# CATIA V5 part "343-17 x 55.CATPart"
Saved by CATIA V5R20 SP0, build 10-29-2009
Part number: 343-17 x 55
Definition: NONE
Nomenclature: 343-17 x 55
Source: Unknown
Description: 343-17 x 55
Bounding box of the stored display mesh (mm): x 0 to 55, y -14 to 14, z -14 to 14
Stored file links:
  C:\Users\Utente\Desktop\IO LAVORO\3D X SITO CF\X SITO\343-348\343-17 x 55.CATPart
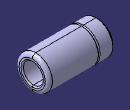
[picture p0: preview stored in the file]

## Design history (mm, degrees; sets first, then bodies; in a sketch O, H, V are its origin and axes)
Body1 "343-17 x 55" (main body)
  Solid1: solid without history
